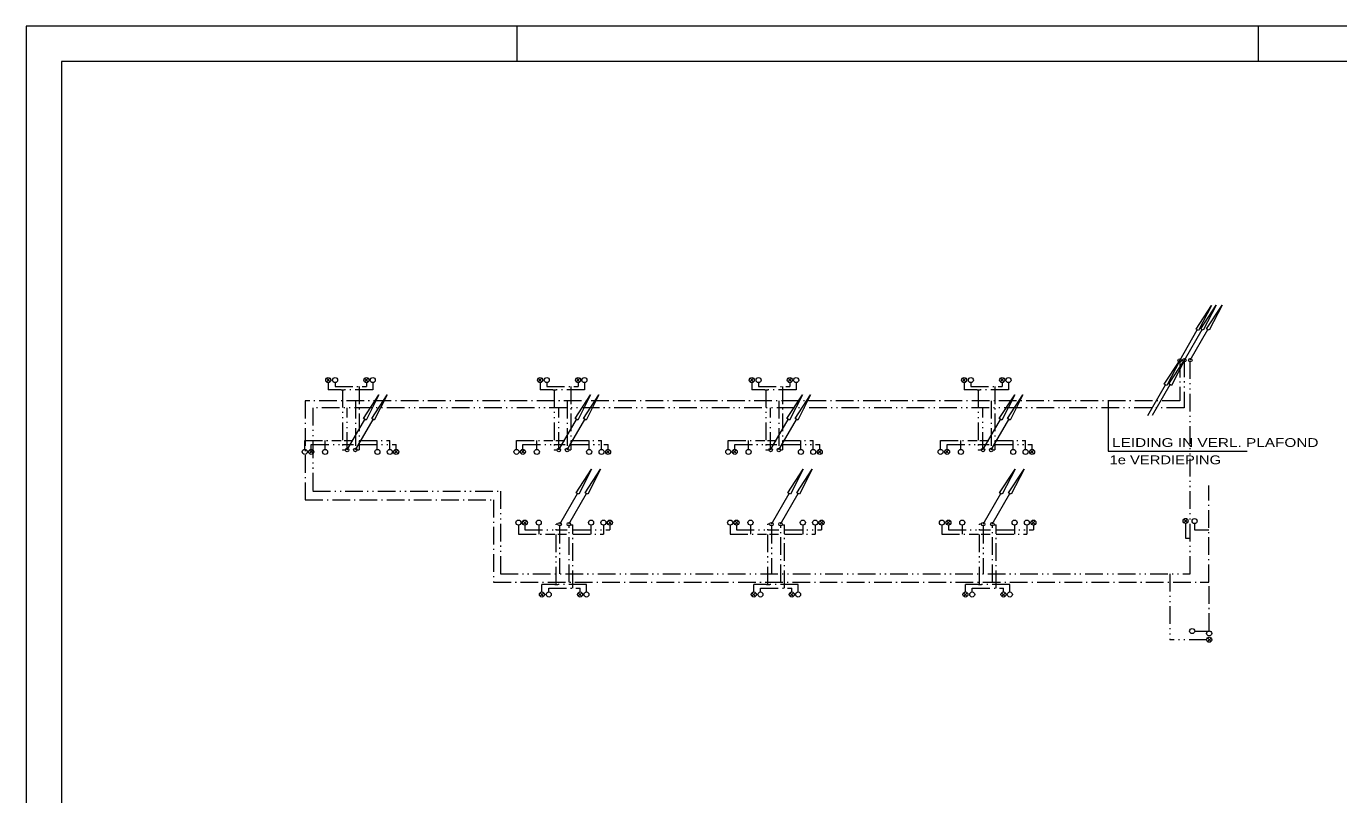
# Model space of a CAD drawing. Extents: x 295824 to 414724, y 24924 to 109024.
# Drawn here: x 295824 to 332992, y 87265 to 109024 of the extents above; entities that cross this region are included whole.
import ezdxf

# ---------------------------------------------------------------- set-up
doc = ezdxf.new("R2010")
doc.units = 0
doc.header["$LTSCALE"] = 100
doc.linetypes.add('DASH_DOUBLE_DOT', pattern=[9.2, 5, -1.2, 0.3, -1.2, 0.3, -1.2])
doc.linetypes.add('DOT_DASHED', pattern=[7.7, 5, -1.2, 0.3, -1.2])
for name, color, linetype, lineweight in [('1', 7, 'Continuous', 13), ('16', 7, 'Continuous', 13), ('30', 7, 'Continuous', 13)]:
    doc.layers.add(name, color=color, linetype=linetype, lineweight=lineweight)

msp = doc.modelspace()

# ---------------------------------------------------------------- linework, layer by layer
at = {"layer": '1'}
for p, q in [((295823.6, 109023.8), (295823.6, 24923.8)), ((309723.6, 108023.8), (309723.6, 109023.8)), ((330723.6, 108023.8), (330723.6, 109023.8))]:
    msp.add_line(p, q, dxfattribs=at)
for points in [[(414723.6, 109023.8), (304995.6, 109023.8), (295823.6, 109023.8)], [(304995.6, 108023.8), (296823.6, 108023.8), (296823.6, 25923.8), (304995.6, 25923.8)], [(304995.6, 25923.8), (413723.6, 25923.8), (413723.6, 108023.8), (304995.6, 108023.8)]]:
    msp.add_lwpolyline(points, dxfattribs=at)
at = {"layer": '30'}
for p, q in [((328487.6, 99561.9), (328987.6, 100427.9)), ((328620.8, 99570.2), (329120.8, 100436.2)), ((328787.4, 99570.2), (329287.4, 100436.2)), ((304424.6, 99060.1), (304323.5, 98959)), ((304327.5, 99058), (304428.8, 98956.7)), ((305503.1, 99060.1), (305402, 98959)), ((305406, 99058), (305507.3, 98956.7)), ((310421, 99060.1), (310319.9, 98959)), ((310323.9, 99058), (310425.2, 98956.7)), ((311499.5, 99060.1), (311398.4, 98959)), ((311402.4, 99058), (311503.7, 98956.7)), ((316417.4, 99060.1), (316316.2, 98959)), ((316320.2, 99058), (316421.6, 98956.7)), ((317495.9, 99060.1), (317394.7, 98959)), ((317398.7, 99058), (317500.1, 98956.7)), ((322430.4, 99060.1), (322329.2, 98959)), ((322333.2, 99058), (322434.6, 98956.7)), ((323508.9, 99060.1), (323407.7, 98959)), ((323411.7, 99058), (323513.1, 98956.7)), ((327720.8, 98011.2), (328220.8, 98877.2)), ((327587.6, 98002.9), (328087.6, 98868.9)), ((326459.3, 98406), (326459.3, 96989.4)), ((304910.2, 97027.3), (305410.2, 97893.3)), ((305143.4, 97027.3), (305643.4, 97893.3)), ((310906.6, 97027.3), (311406.6, 97893.3)), ((311139.8, 97027.3), (311639.8, 97893.3)), ((316903, 97027.3), (317403, 97893.3)), ((317136.1, 97027.3), (317636.1, 97893.3)), ((322916, 97027.3), (323416, 97893.3)), ((323149.2, 97027.3), (323649.2, 97893.3)), ((303941.6, 97026.8), (303840.5, 96925.7)), ((303844.5, 97024.7), (303945.8, 96923.4)), ((306349.4, 97024.9), (306248.3, 96923.7)), ((306252.3, 97022.8), (306353.6, 96921.4)), ((309938, 97026.8), (309836.8, 96925.7)), ((309840.8, 97024.7), (309942.2, 96923.4)), ((312345.8, 97024.9), (312244.7, 96923.7)), ((312248.7, 97022.8), (312350, 96921.4)), ((315934.3, 97026.8), (315833.2, 96925.7)), ((315837.2, 97024.7), (315938.5, 96923.4)), ((318342.2, 97024.9), (318241, 96923.7)), ((318245, 97022.8), (318346.4, 96921.4)), ((321947.4, 97026.8), (321846.2, 96925.7)), ((321850.2, 97024.7), (321951.5, 96923.4)), ((324355.2, 97024.9), (324254, 96923.7)), ((324258, 97022.8), (324359.4, 96921.4)), ((326459.3, 96989.4), (330401.9, 96989.4)), ((310931.7, 94927.3), (311431.7, 95793.3)), ((311187.8, 94927.3), (311687.8, 95793.3)), ((316928, 94927.3), (317428, 95793.3)), ((317184.1, 94927.3), (317684.1, 95793.3)), ((322924.3, 94927.3), (323424.3, 95793.3)), ((323180.4, 94927.3), (323680.4, 95793.3)), ((309992.2, 94915.4), (309891.1, 95016.5)), ((309895.1, 94917.5), (309996.4, 95018.8)), ((312400.1, 94917.3), (312298.9, 95018.5)), ((312302.9, 94919.4), (312404.3, 95020.8)), ((315988.5, 94915.4), (315887.4, 95016.5)), ((315891.4, 94917.5), (315992.7, 95018.8)), ((318396.4, 94917.3), (318295.2, 95018.5)), ((318299.2, 94919.4), (318400.6, 95020.8)), ((321984.8, 94915.4), (321883.7, 95016.5)), ((321887.7, 94917.5), (321989, 95018.8)), ((324392.7, 94917.3), (324291.5, 95018.5)), ((324295.5, 94919.4), (324396.9, 95020.8)), ((328708.8, 94966.4), (328607.5, 95067.7)), ((328710.9, 95063.5), (328609.7, 94962.3)), ((310475.3, 92882.1), (310374.1, 92983.2)), ((310378.1, 92884.2), (310479.5, 92985.5)), ((311553.8, 92882.1), (311452.6, 92983.2)), ((311456.6, 92884.2), (311558, 92985.5)), ((316471.6, 92882.1), (316370.4, 92983.2)), ((316374.4, 92884.2), (316475.8, 92985.5)), ((317550.1, 92882.1), (317448.9, 92983.2)), ((317452.9, 92884.2), (317554.3, 92985.5)), ((322467.9, 92882.1), (322366.7, 92983.2)), ((322370.7, 92884.2), (322472.1, 92985.5)), ((323546.4, 92882.1), (323445.2, 92983.2)), ((323449.2, 92884.2), (323550.6, 92985.5)), ((329375.1, 91603.9), (329273.7, 91705.2)), ((329377.2, 91701), (329276, 91599.9))]:
    msp.add_line(p, q, dxfattribs=at)
at = {"layer": '30', "linetype": 'DASH_DOUBLE_DOT'}
for p, q in [((328615.2, 99591.9), (328615.2, 98216.9)), ((328781.8, 93517), (328781.8, 99540.2)), ((304377.2, 98934.7), (304377.2, 98725.4)), ((305634.8, 98934.7), (305634.8, 98725.4)), ((310373.6, 98934.7), (310373.6, 98725.4)), ((311631.1, 98934.7), (311631.1, 98725.4)), ((316370, 98934.7), (316370, 98725.4)), ((317627.5, 98934.7), (317627.5, 98725.4)), ((322383, 98934.7), (322383, 98725.4)), ((323640.5, 98934.7), (323640.5, 98725.4)), ((304743.6, 98725.4), (304377.2, 98725.4)), ((304743.6, 98725.4), (304831.1, 98725.4)), ((304776.9, 98725.4), (304776.9, 97022.7)), ((305634.8, 98725.4), (304831.1, 98725.4)), ((310740, 98725.4), (310373.6, 98725.4)), ((310740, 98725.4), (310827.4, 98725.4)), ((310773.3, 98725.4), (310773.3, 97022.7)), ((311631.1, 98725.4), (310827.4, 98725.4)), ((316736.4, 98725.4), (316370, 98725.4)), ((316736.4, 98725.4), (316823.8, 98725.4)), ((316769.7, 98725.4), (316769.7, 97022.7)), ((317627.5, 98725.4), (316823.8, 98725.4)), ((322749.4, 98725.4), (322383, 98725.4)), ((322749.4, 98725.4), (322836.8, 98725.4)), ((322782.7, 98725.4), (322782.7, 97022.7)), ((323640.5, 98725.4), (322836.8, 98725.4)), ((328615.2, 98216.9), (303939, 98216.9)), ((304910.2, 97027.3), (304910.2, 98216.9)), ((310906.6, 97027.3), (310906.6, 98216.9)), ((316903, 97027.3), (316903, 98216.9)), ((322916, 97027.3), (322916, 98216.9)), ((303894.2, 97044.8), (303894.2, 97178.5)), ((304860.2, 97022.7), (304776.9, 97022.7)), ((305264.9, 97178.5), (306302, 97178.5)), ((306302, 97042.8), (306302, 97178.5)), ((309890.5, 97044.8), (309890.5, 97178.5)), ((310856.6, 97022.7), (310773.3, 97022.7)), ((311261.3, 97178.5), (312298.4, 97178.5)), ((312298.4, 97042.8), (312298.4, 97178.5)), ((315886.9, 97044.8), (315886.9, 97178.5)), ((316853, 97022.7), (316769.7, 97022.7)), ((317257.7, 97178.5), (318294.7, 97178.5)), ((318294.7, 97042.8), (318294.7, 97178.5)), ((321899.9, 97044.8), (321899.9, 97178.5)), ((322866, 97022.7), (322782.7, 97022.7)), ((323270.7, 97178.5), (324307.8, 97178.5)), ((324307.8, 97042.8), (324307.8, 97178.5)), ((309944.8, 94897.4), (309944.8, 94763.7)), ((310883.6, 94927.8), (310827.6, 94927.8)), ((310827.6, 93216.8), (310827.6, 94927.8)), ((310927.5, 94881.6), (310927.5, 93517)), ((312352.6, 94899.4), (312352.6, 94763.7)), ((315941.1, 94897.4), (315941.1, 94763.7)), ((316879.9, 94927.8), (316823.9, 94927.8)), ((316823.9, 93216.8), (316823.9, 94927.8)), ((316923.8, 94881.6), (316923.8, 93517)), ((318348.9, 94899.4), (318348.9, 94763.7)), ((321937.4, 94897.4), (321937.4, 94763.7)), ((322876.2, 94927.8), (322820.2, 94927.8)), ((322820.2, 93216.8), (322820.2, 94927.8)), ((322920.1, 94881.6), (322920.1, 93517)), ((324345.2, 94899.4), (324345.2, 94763.7)), ((328657.2, 94944.4), (328657.2, 94528.6)), ((311315.6, 94763.7), (312352.6, 94763.7)), ((317311.9, 94763.7), (318348.9, 94763.7)), ((323308.2, 94763.7), (324345.2, 94763.7)), ((328657.2, 94528.6), (328781.8, 94528.6)), ((328212.7, 93520.3), (328212.7, 91653.6)), ((310427.9, 93007.5), (310427.9, 93216.8)), ((310794.3, 93216.8), (310427.9, 93216.8)), ((310794.3, 93216.8), (310881.7, 93216.8)), ((311685.4, 93216.8), (310881.7, 93216.8)), ((311685.4, 93007.5), (311685.4, 93216.8)), ((316424.2, 93007.5), (316424.2, 93216.8)), ((316790.6, 93216.8), (316424.2, 93216.8)), ((316790.6, 93216.8), (316878, 93216.8)), ((317681.7, 93216.8), (316878, 93216.8)), ((317681.7, 93007.5), (317681.7, 93216.8)), ((322420.5, 93007.5), (322420.5, 93216.8)), ((322786.9, 93216.8), (322420.5, 93216.8)), ((322786.9, 93216.8), (322874.3, 93216.8)), ((323678, 93216.8), (322874.3, 93216.8)), ((323678, 93007.5), (323678, 93216.8)), ((329251.8, 91653.6), (328212.7, 91653.6))]:
    msp.add_line(p, q, dxfattribs=at)
at = {"layer": '30', "linetype": 'DOT_DASHED'}
for p, q in [((305455.7, 98934.7), (305455.7, 98823.3)), ((311452.1, 98934.7), (311452.1, 98823.3)), ((317448.4, 98934.7), (317448.4, 98823.3)), ((323461.5, 98934.7), (323461.5, 98823.3)), ((305251.7, 98826.8), (305251.7, 97031)), ((311248, 98826.8), (311248, 97031)), ((317244.4, 98826.8), (317244.4, 97031)), ((323257.4, 98826.8), (323257.4, 97031)), ((305143.4, 98416.9), (305143.4, 97052.3)), ((311139.8, 98416.9), (311139.8, 97052.3)), ((317136.1, 98416.9), (317136.1, 97052.3)), ((323149.2, 98416.9), (323149.2, 97052.3)), ((303711, 97044.8), (303711, 97299.4)), ((303711, 97299.4), (304743.6, 97299.4)), ((304286.6, 97042.8), (304286.6, 97299.4)), ((304822.8, 97299.4), (305076.8, 97299.4)), ((305189.2, 97031), (305251.7, 97031)), ((305251.7, 97299.4), (306118.8, 97299.4)), ((305764.9, 97042.8), (305764.9, 97299.4)), ((306118.8, 97042.8), (306118.8, 97299.4)), ((309707.3, 97044.8), (309707.3, 97299.4)), ((309707.3, 97299.4), (310740, 97299.4)), ((310283, 97042.8), (310283, 97299.4)), ((310819.1, 97299.4), (311073.1, 97299.4)), ((311185.6, 97031), (311248, 97031)), ((311248, 97299.4), (312115.2, 97299.4)), ((311761.2, 97042.8), (311761.2, 97299.4)), ((312115.2, 97042.8), (312115.2, 97299.4)), ((315703.7, 97044.8), (315703.7, 97299.4)), ((315703.7, 97299.4), (316736.4, 97299.4)), ((316279.3, 97042.8), (316279.3, 97299.4)), ((316815.5, 97299.4), (317069.5, 97299.4)), ((317181.9, 97031), (317244.4, 97031)), ((317244.4, 97299.4), (318111.5, 97299.4)), ((317757.6, 97042.8), (317757.6, 97299.4)), ((318111.5, 97042.8), (318111.5, 97299.4)), ((321716.7, 97044.8), (321716.7, 97299.4)), ((321716.7, 97299.4), (322749.4, 97299.4)), ((322292.4, 97042.8), (322292.4, 97299.4)), ((322828.5, 97299.4), (323082.5, 97299.4)), ((323194.9, 97031), (323257.4, 97031)), ((323257.4, 97299.4), (324124.5, 97299.4)), ((323770.6, 97042.8), (323770.6, 97299.4)), ((324124.5, 97042.8), (324124.5, 97299.4)), ((329314.8, 93283.7), (329314.8, 96016.9)), ((309761.6, 94897.4), (309761.6, 94642.8)), ((310337.2, 94899.4), (310337.2, 94642.8)), ((311194, 93283.7), (311194, 94889.9)), ((311239.8, 94911.2), (311302.3, 94911.2)), ((311302.3, 93115.4), (311302.3, 94911.2)), ((311815.5, 94899.4), (311815.5, 94642.8)), ((312169.4, 94899.4), (312169.4, 94642.8)), ((315757.9, 94897.4), (315757.9, 94642.8)), ((316333.5, 94899.4), (316333.5, 94642.8)), ((317190.3, 93283.7), (317190.3, 94889.9)), ((317236.1, 94911.2), (317298.6, 94911.2)), ((317298.6, 93115.4), (317298.6, 94911.2)), ((317811.8, 94899.4), (317811.8, 94642.8)), ((318165.7, 94899.4), (318165.7, 94642.8)), ((321754.2, 94897.4), (321754.2, 94642.8)), ((322329.8, 94899.4), (322329.8, 94642.8)), ((323186.6, 93283.7), (323186.6, 94889.9)), ((323232.4, 94911.2), (323294.9, 94911.2)), ((323294.9, 93115.4), (323294.9, 94911.2)), ((323808.1, 94899.4), (323808.1, 94642.8)), ((324162, 94899.4), (324162, 94642.8)), ((309761.6, 94642.8), (310794.3, 94642.8)), ((310873.4, 94642.8), (311127.4, 94642.8)), ((311302.3, 94642.8), (312169.4, 94642.8)), ((315757.9, 94642.8), (316790.6, 94642.8)), ((316869.7, 94642.8), (317123.7, 94642.8)), ((317298.6, 94642.8), (318165.7, 94642.8)), ((321754.2, 94642.8), (322786.9, 94642.8)), ((322866, 94642.8), (323120, 94642.8)), ((323294.9, 94642.8), (324162, 94642.8)), ((311506.3, 93007.5), (311506.3, 93118.9)), ((317502.6, 93007.5), (317502.6, 93118.9)), ((323498.9, 93007.5), (323498.9, 93118.9)), ((329323.4, 91904.3), (329323.4, 93283.7)), ((328912.3, 91895.3), (329328.7, 91895.3))]:
    msp.add_line(p, q, dxfattribs=at)
at = {"layer": '30'}
for points in [[(329387.6, 101120.9), (329023.6, 100406.9), (328951.6, 100448.9)], [(329520.8, 101129.2), (329156.8, 100415.2), (329084.8, 100457.2)], [(329687.4, 101129.2), (329323.4, 100415.2), (329251.4, 100457.2)], [(328487.6, 99561.9), (328123.6, 98847.9), (328051.6, 98889.9)], [(328620.8, 99570.2), (328256.8, 98856.2), (328184.8, 98898.2)], [(305810.2, 98586.3), (305446.2, 97872.3), (305374.2, 97914.3)], [(306043.4, 98586.3), (305679.4, 97872.3), (305607.4, 97914.3)], [(311806.6, 98586.3), (311442.6, 97872.3), (311370.6, 97914.3)], [(312039.8, 98586.3), (311675.8, 97872.3), (311603.8, 97914.3)], [(317803, 98586.3), (317439, 97872.3), (317367, 97914.3)], [(318036.1, 98586.3), (317672.1, 97872.3), (317600.1, 97914.3)], [(323816, 98586.3), (323452, 97872.3), (323380, 97914.3)], [(324049.2, 98586.3), (323685.2, 97872.3), (323613.2, 97914.3)], [(311831.7, 96486.3), (311467.7, 95772.3), (311395.7, 95814.3)], [(312087.8, 96486.3), (311723.8, 95772.3), (311651.8, 95814.3)], [(317828, 96486.3), (317464, 95772.3), (317392, 95814.3)], [(318084.1, 96486.3), (317720.1, 95772.3), (317648.1, 95814.3)], [(323824.3, 96486.3), (323460.3, 95772.3), (323388.3, 95814.3)], [(324080.4, 96486.3), (323716.4, 95772.3), (323644.4, 95814.3)]]:
    msp.add_lwpolyline(points, close=True, dxfattribs=at)
at = {"layer": '30', "linetype": 'DOT_DASHED'}
for points in [[(328490.3, 99583.5), (328490.3, 98416.9), (303722.5, 98416.9), (303722.5, 95616.9), (309052.5, 95616.9), (309052.5, 93283.7), (329314.8, 93283.7)], [(304568.8, 98934.7), (304568.8, 98823.3), (305455.7, 98823.3)], [(310565.1, 98934.7), (310565.1, 98823.3), (311452.1, 98823.3)], [(316561.5, 98934.7), (316561.5, 98823.3), (317448.4, 98823.3)], [(322574.5, 98934.7), (322574.5, 98823.3), (323461.5, 98823.3)], [(328911.2, 94944.3), (328911.2, 94770.3), (329314.8, 94770.3)], [(310619.4, 93007.5), (310619.4, 93118.9), (311506.3, 93118.9)], [(316615.7, 93007.5), (316615.7, 93118.9), (317502.6, 93118.9)], [(322612, 93007.5), (322612, 93118.9), (323498.9, 93118.9)]]:
    msp.add_lwpolyline(points, dxfattribs=at)
at = {"layer": '30', "linetype": 'DASH_DOUBLE_DOT'}
for points in [[(303939, 98216.9), (303939, 95858.6), (309252.3, 95858.6), (309252.3, 93517), (328781.8, 93517)], [(303894.2, 97178.5), (304776.9, 97178.5), (305090, 97178.5)], [(309890.5, 97178.5), (310773.3, 97178.5), (311086.4, 97178.5)], [(315886.9, 97178.5), (316769.7, 97178.5), (317082.8, 97178.5)], [(321899.9, 97178.5), (322782.7, 97178.5), (323095.8, 97178.5)], [(309944.8, 94763.7), (310827.6, 94763.7), (311140.7, 94763.7)], [(315941.1, 94763.7), (316823.9, 94763.7), (317137, 94763.7)], [(321937.4, 94763.7), (322820.2, 94763.7), (323133.3, 94763.7)]]:
    msp.add_lwpolyline(points, dxfattribs=at)
at = {"layer": '30'}
for centre, radius in [((328620.8, 99569.9), 50), ((328620.8, 99569.9), 50), ((328787.4, 99569.9), 50), ((328487.6, 99561.6), 50), ((328487.6, 99561.6), 50), ((304377.2, 99006.4), 71.7), ((304568.8, 99006.4), 71.7), ((305455.7, 99006.4), 71.7), ((305634.8, 99006.4), 71.7), ((310373.6, 99006.4), 71.7), ((310565.1, 99006.4), 71.7), ((311452.1, 99006.4), 71.7), ((311631.1, 99006.4), 71.7), ((316369.9, 99006.4), 71.7), ((316561.5, 99006.4), 71.7), ((317448.4, 99006.4), 71.7), ((317627.5, 99006.4), 71.7), ((322383, 99006.4), 71.7), ((322574.5, 99006.4), 71.7), ((323461.5, 99006.4), 71.7), ((323640.5, 99006.4), 71.7), ((303711, 96973.1), 71.7), ((303894.2, 96973.1), 71.7), ((304286.6, 96971.2), 71.7), ((304910.2, 97027), 50), ((305143.4, 97027), 50), ((305769, 96971.2), 71.7), ((306118.8, 96971.2), 71.7), ((306302, 96971.1), 71.7), ((309707.3, 96973.1), 71.7), ((309890.5, 96973.1), 71.7), ((310283, 96971.2), 71.7), ((310906.6, 97027), 50), ((311139.8, 97027), 50), ((311765.4, 96971.2), 71.7), ((312115.2, 96971.2), 71.7), ((312298.4, 96971.1), 71.7), ((315703.7, 96973.1), 71.7), ((315886.9, 96973.1), 71.7), ((316279.3, 96971.2), 71.7), ((316902.9, 97027), 50), ((317136.1, 97027), 50), ((317761.8, 96971.2), 71.7), ((318111.5, 96971.2), 71.7), ((318294.7, 96971.1), 71.7), ((321716.7, 96973.1), 71.7), ((321899.9, 96973.1), 71.7), ((322292.4, 96971.2), 71.7), ((322916, 97027), 50), ((323149.2, 97027), 50), ((323774.8, 96971.2), 71.7), ((324124.6, 96971.2), 71.7), ((324307.8, 96971.1), 71.7), ((309761.6, 94969.1), 71.7), ((309944.8, 94969.1), 71.7), ((310337.2, 94971), 71.7), ((310931.7, 94927), 50), ((311187.8, 94927), 50), ((311819.7, 94971), 71.7), ((312169.4, 94971), 71.7), ((312352.6, 94971.1), 71.7), ((315757.9, 94969.1), 71.7), ((315941.1, 94969.1), 71.7), ((316333.5, 94971), 71.7), ((316928, 94927), 50), ((317184.1, 94927), 50), ((317816, 94971), 71.7), ((318165.7, 94971), 71.7), ((318348.9, 94971.1), 71.7), ((321754.2, 94969.1), 71.7), ((321937.4, 94969.1), 71.7), ((322329.8, 94971), 71.7), ((322924.3, 94927), 50), ((323180.4, 94927), 50), ((323812.3, 94971), 71.7), ((324162, 94971), 71.7), ((324345.2, 94971.1), 71.7), ((328657.2, 95016.1), 71.7), ((328911.2, 95015.9), 71.7), ((310427.8, 92935.8), 71.7), ((310619.4, 92935.8), 71.7), ((311506.3, 92935.8), 71.7), ((311685.4, 92935.8), 71.7), ((316424.1, 92935.8), 71.7), ((316615.7, 92935.8), 71.7), ((317502.6, 92935.8), 71.7), ((317681.7, 92935.8), 71.7), ((322420.4, 92935.8), 71.7), ((322612, 92935.8), 71.7), ((323498.9, 92935.8), 71.7), ((323678, 92935.8), 71.7), ((328840.4, 91899.3), 71.7), ((329323.4, 91832.7), 71.7), ((329323.4, 91653.6), 71.7)]:
    msp.add_circle(centre, radius, dxfattribs=at)

# ---------------------------------------------------------------- texts
at = {"layer": '16'}
for s, width, p in [('LEIDING IN VERL. PLAFOND', 1.3, (326574.3, 97111.7)), ('1e VERDIEPING', 1.25, (326501.7, 96622.3))]:
    msp.add_text(s, height=250, dxfattribs=dict(at, width=width)).set_placement(p)

doc.saveas('drawing.dxf')
